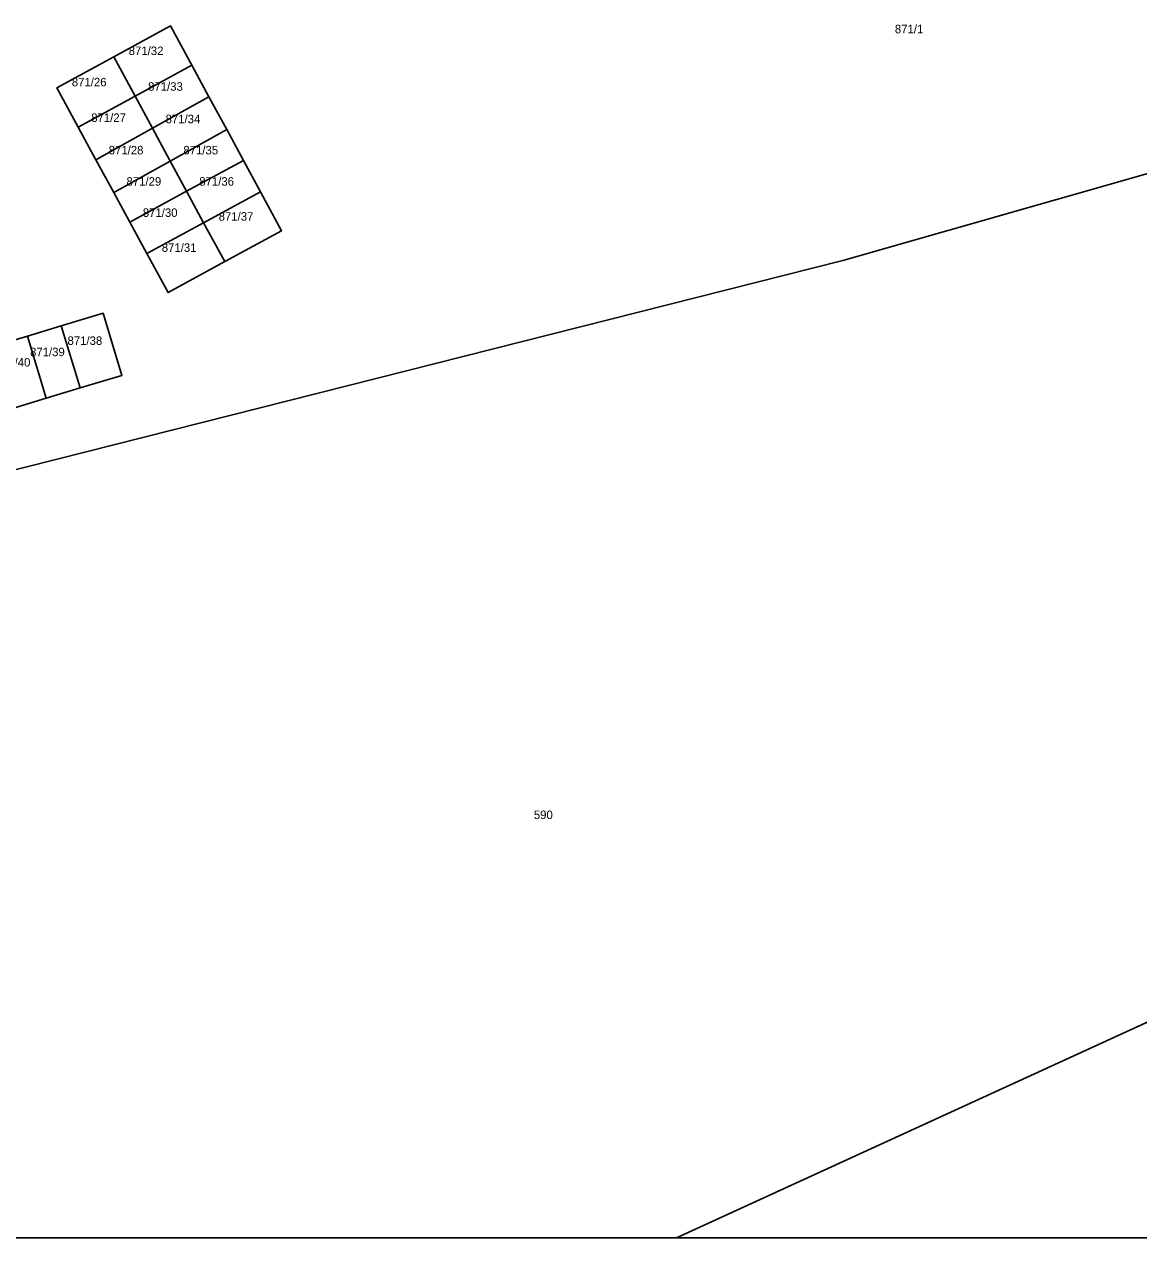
# Model space of a CAD drawing. Extents: x -873642 to -872917, y -1012962 to -1012567.
# Drawn here: x -873284.9 to -873173.4, y -1012961.7 to -1012840.3 of the extents above; entities that cross this region are included whole.
import ezdxf

# ---------------------------------------------------------------- set-up
doc = ezdxf.new("R2010")
doc.units = 0
for name, color, linetype in [('cisla_parcelni_kn', 7, 'Continuous'), ('parcely_kn', 7, 'Continuous'), ('stavebni_objekty_ostatni', 7, 'Continuous')]:
    doc.layers.add(name, color=color, linetype=linetype)

msp = doc.modelspace()

# ---------------------------------------------------------------- linework, layer by layer
at = {"layer": 'parcely_kn'}
for p, q in [((-873296.12, -1012961.69), (-873219.62, -1012961.69)), ((-873296.12, -1012961.69), (-873219.62, -1012961.69)), ((-873219.62, -1012961.69), (-873035.97, -1012961.69)), ((-873219.62, -1012961.69), (-873035.97, -1012961.69))]:
    msp.add_line(p, q, dxfattribs=at)
for points in [[(-873277.69, -1012853.84), (-873275.91, -1012857.12), (-873274.3, -1012860.07), (-873272.59, -1012863.23), (-873270.47, -1012867.12), (-873264.8, -1012864.03), (-873259.11, -1012860.94), (-873261.23, -1012857.03), (-873262.92, -1012853.9), (-873264.6, -1012850.81), (-873266.38, -1012847.53), (-873268.09, -1012844.36), (-873270.21, -1012840.45), (-873275.9, -1012843.54), (-873281.61, -1012846.64), (-873279.46, -1012850.59)], [(-873277.69, -1012853.84), (-873275.91, -1012857.12), (-873274.3, -1012860.07), (-873272.59, -1012863.23), (-873270.47, -1012867.12), (-873264.8, -1012864.03), (-873259.11, -1012860.94), (-873261.23, -1012857.03), (-873262.92, -1012853.9), (-873264.6, -1012850.81), (-873266.38, -1012847.53), (-873268.09, -1012844.36), (-873270.21, -1012840.45), (-873275.9, -1012843.54), (-873281.61, -1012846.64), (-873279.46, -1012850.59)], [(-873275.9, -1012843.54), (-873270.21, -1012840.45), (-873268.09, -1012844.36), (-873273.77, -1012847.47)], [(-873275.9, -1012843.54), (-873270.21, -1012840.45), (-873268.09, -1012844.36), (-873273.77, -1012847.47)], [(-873281.61, -1012846.64), (-873275.9, -1012843.54), (-873273.77, -1012847.47), (-873279.46, -1012850.59)], [(-873281.61, -1012846.64), (-873275.9, -1012843.54), (-873273.77, -1012847.47), (-873279.46, -1012850.59)], [(-873268.09, -1012844.36), (-873266.38, -1012847.53), (-873272.03, -1012850.68), (-873273.77, -1012847.47)], [(-873268.09, -1012844.36), (-873266.38, -1012847.53), (-873272.03, -1012850.68), (-873273.77, -1012847.47)], [(-873272.03, -1012850.68), (-873277.69, -1012853.84), (-873279.46, -1012850.59), (-873273.77, -1012847.47)], [(-873272.03, -1012850.68), (-873277.69, -1012853.84), (-873279.46, -1012850.59), (-873273.77, -1012847.47)], [(-873266.38, -1012847.53), (-873264.6, -1012850.81), (-873270.25, -1012853.96), (-873272.03, -1012850.68)], [(-873266.38, -1012847.53), (-873264.6, -1012850.81), (-873270.25, -1012853.96), (-873272.03, -1012850.68)], [(-873270.25, -1012853.96), (-873275.91, -1012857.12), (-873277.69, -1012853.84), (-873272.03, -1012850.68)], [(-873270.25, -1012853.96), (-873275.91, -1012857.12), (-873277.69, -1012853.84), (-873272.03, -1012850.68)], [(-873264.6, -1012850.81), (-873262.92, -1012853.9), (-873268.62, -1012856.99), (-873270.25, -1012853.96)], [(-873264.6, -1012850.81), (-873262.92, -1012853.9), (-873268.62, -1012856.99), (-873270.25, -1012853.96)], [(-873268.62, -1012856.99), (-873274.3, -1012860.07), (-873275.91, -1012857.12), (-873270.25, -1012853.96)], [(-873268.62, -1012856.99), (-873274.3, -1012860.07), (-873275.91, -1012857.12), (-873270.25, -1012853.96)], [(-873262.92, -1012853.9), (-873261.23, -1012857.03), (-873266.91, -1012860.13), (-873268.62, -1012856.99)], [(-873262.92, -1012853.9), (-873261.23, -1012857.03), (-873266.91, -1012860.13), (-873268.62, -1012856.99)], [(-873266.91, -1012860.13), (-873272.59, -1012863.23), (-873274.3, -1012860.07), (-873268.62, -1012856.99)], [(-873266.91, -1012860.13), (-873272.59, -1012863.23), (-873274.3, -1012860.07), (-873268.62, -1012856.99)], [(-873261.23, -1012857.03), (-873259.11, -1012860.94), (-873264.8, -1012864.03), (-873266.91, -1012860.13)], [(-873261.23, -1012857.03), (-873259.11, -1012860.94), (-873264.8, -1012864.03), (-873266.91, -1012860.13)], [(-873264.8, -1012864.03), (-873270.47, -1012867.12), (-873272.59, -1012863.23), (-873266.91, -1012860.13)], [(-873264.8, -1012864.03), (-873270.47, -1012867.12), (-873272.59, -1012863.23), (-873266.91, -1012860.13)], [(-873276.97, -1012869.19), (-873275.09, -1012875.41), (-873279.27, -1012876.67), (-873281.15, -1012870.45)], [(-873276.97, -1012869.19), (-873275.09, -1012875.41), (-873279.27, -1012876.67), (-873281.15, -1012870.45)], [(-873281.15, -1012870.45), (-873279.27, -1012876.67), (-873282.65, -1012877.69), (-873284.53, -1012871.47)], [(-873281.15, -1012870.45), (-873279.27, -1012876.67), (-873282.65, -1012877.69), (-873284.53, -1012871.47)], [(-873287.92, -1012872.5), (-873284.53, -1012871.47), (-873282.65, -1012877.69), (-873286.04, -1012878.72)], [(-873287.92, -1012872.5), (-873284.53, -1012871.47), (-873282.65, -1012877.69), (-873286.04, -1012878.72)]]:
    msp.add_lwpolyline(points, close=True, dxfattribs=at)
for points in [[(-873149.77, -1012848.73), (-873202.95, -1012863.9), (-873307.96, -1012890.45), (-873318.36, -1012895.27), (-873328.54, -1012899.56), (-873340.69, -1012904.93), (-873416.15, -1012938.7), (-873417.98, -1012939.52), (-873435.72, -1012947.37), (-873445.76, -1012897.62), (-873478.14, -1012904.47), (-873481.91, -1012884.93)], [(-873149.77, -1012848.73), (-873202.95, -1012863.9), (-873307.96, -1012890.45), (-873318.36, -1012895.27), (-873328.54, -1012899.56), (-873340.69, -1012904.93), (-873416.15, -1012938.7), (-873417.98, -1012939.52), (-873435.72, -1012947.37), (-873445.76, -1012897.62), (-873478.14, -1012904.47), (-873481.91, -1012884.93)], [(-873219.62, -1012961.69), (-873165.87, -1012937.08), (-873157.54, -1012937.35), (-873150.44, -1012877.16), (-873149.77, -1012848.73), (-873202.95, -1012863.9), (-873307.96, -1012890.45), (-873318.36, -1012895.27), (-873296.12, -1012961.69)], [(-873219.62, -1012961.69), (-873165.87, -1012937.08), (-873157.54, -1012937.35), (-873150.44, -1012877.16), (-873149.77, -1012848.73), (-873202.95, -1012863.9), (-873307.96, -1012890.45), (-873318.36, -1012895.27), (-873296.12, -1012961.69)], [(-872916.93, -1012866.59), (-872924.74, -1012869.07), (-872940.25, -1012872.81), (-872949.32, -1012875.06), (-872947.03, -1012888.69), (-873054.93, -1012914.29), (-873056.89, -1012904.69), (-873081.5, -1012916.68), (-873144.57, -1012937.76), (-873157.54, -1012937.35), (-873165.87, -1012937.08), (-873219.62, -1012961.69)], [(-872916.93, -1012866.59), (-872924.74, -1012869.07), (-872940.25, -1012872.81), (-872949.32, -1012875.06), (-872947.03, -1012888.69), (-873054.93, -1012914.29), (-873056.89, -1012904.69), (-873081.5, -1012916.68), (-873144.57, -1012937.76), (-873157.54, -1012937.35), (-873165.87, -1012937.08), (-873219.62, -1012961.69)], [(-873286.04, -1012878.72), (-873282.65, -1012877.69), (-873279.27, -1012876.67), (-873275.09, -1012875.41), (-873276.97, -1012869.19), (-873281.15, -1012870.45), (-873284.53, -1012871.47), (-873287.92, -1012872.5)], [(-873286.04, -1012878.72), (-873282.65, -1012877.69), (-873279.27, -1012876.67), (-873275.09, -1012875.41), (-873276.97, -1012869.19), (-873281.15, -1012870.45), (-873284.53, -1012871.47), (-873287.92, -1012872.5)]]:
    msp.add_lwpolyline(points, dxfattribs=at)
at = {"layer": 'stavebni_objekty_ostatni'}
for points in [[(-873275.9, -1012843.54), (-873270.21, -1012840.45), (-873268.09, -1012844.36), (-873273.77, -1012847.47)], [(-873281.61, -1012846.64), (-873275.9, -1012843.54), (-873273.77, -1012847.47), (-873279.46, -1012850.59)], [(-873268.09, -1012844.36), (-873266.38, -1012847.53), (-873272.03, -1012850.68), (-873273.77, -1012847.47)], [(-873277.69, -1012853.84), (-873279.46, -1012850.59), (-873273.77, -1012847.47), (-873272.03, -1012850.68)], [(-873266.38, -1012847.53), (-873264.6, -1012850.81), (-873270.25, -1012853.96), (-873272.03, -1012850.68)], [(-873275.91, -1012857.12), (-873277.69, -1012853.84), (-873272.03, -1012850.68), (-873270.25, -1012853.96)], [(-873264.6, -1012850.81), (-873262.92, -1012853.9), (-873268.62, -1012856.99), (-873270.25, -1012853.96)], [(-873274.3, -1012860.07), (-873275.91, -1012857.12), (-873270.25, -1012853.96), (-873268.62, -1012856.99)], [(-873262.92, -1012853.9), (-873261.23, -1012857.03), (-873266.91, -1012860.13), (-873268.62, -1012856.99)], [(-873272.59, -1012863.23), (-873274.3, -1012860.07), (-873268.62, -1012856.99), (-873266.91, -1012860.13)], [(-873259.11, -1012860.94), (-873264.8, -1012864.03), (-873266.91, -1012860.13), (-873261.23, -1012857.03)], [(-873264.8, -1012864.03), (-873270.47, -1012867.12), (-873272.59, -1012863.23), (-873266.91, -1012860.13)], [(-873276.97, -1012869.19), (-873275.09, -1012875.41), (-873279.27, -1012876.67), (-873281.15, -1012870.45)], [(-873282.65, -1012877.69), (-873284.53, -1012871.47), (-873281.15, -1012870.45), (-873279.27, -1012876.67)], [(-873287.92, -1012872.5), (-873284.53, -1012871.47), (-873282.65, -1012877.69), (-873286.04, -1012878.72)]]:
    msp.add_lwpolyline(points, close=True, dxfattribs=at)

# ---------------------------------------------------------------- texts
at = {"layer": 'cisla_parcelni_kn'}
for s, p in [('871/1', (-873197.76, -1012841.18)), ('871/1', (-873197.76, -1012841.18)), ('871/32', (-873274.41, -1012843.36)), ('871/32', (-873274.41, -1012843.36)), ('871/26', (-873280.1, -1012846.49)), ('871/26', (-873280.1, -1012846.49)), ('871/33', (-873272.47, -1012846.93)), ('871/33', (-873272.47, -1012846.93)), ('871/27', (-873278.16, -1012850.05)), ('871/27', (-873278.16, -1012850.05)), ('871/34', (-873270.72, -1012850.18)), ('871/34', (-873270.72, -1012850.18)), ('871/28', (-873276.41, -1012853.3)), ('871/28', (-873276.41, -1012853.3)), ('871/35', (-873268.94, -1012853.3)), ('871/35', (-873268.94, -1012853.3)), ('871/29', (-873274.63, -1012856.43)), ('871/29', (-873274.63, -1012856.43)), ('871/36', (-873267.35, -1012856.43)), ('871/36', (-873267.35, -1012856.43)), ('871/30', (-873273, -1012859.55)), ('871/30', (-873273, -1012859.55)), ('871/37', (-873265.41, -1012859.93)), ('871/37', (-873265.41, -1012859.93)), ('871/31', (-873271.1, -1012863.05)), ('871/31', (-873271.1, -1012863.05)), ('871/38', (-873280.53, -1012872.36)), ('871/38', (-873280.53, -1012872.36)), ('871/39', (-873284.28, -1012873.49)), ('871/39', (-873284.28, -1012873.49)), ('871/40', (-873287.72, -1012874.52)), ('871/40', (-873287.72, -1012874.52)), ('590', (-873233.88, -1012919.8)), ('590', (-873233.88, -1012919.8))]:
    msp.add_text(s, height=0.85, dxfattribs=at).set_placement(p)

doc.saveas('drawing.dxf')
